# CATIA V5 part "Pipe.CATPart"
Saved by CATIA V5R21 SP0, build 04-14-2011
Part number: Pipe
Bounding box of the stored display mesh (mm): x -50 to 50, y 0 to 150, z -50 to 50
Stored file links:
  D:\CATIA V5R21 E-RESOURCES\CATIA-V5R21\catia-v5r21-Prts\c12_catia_v5r21_prt\c12_catia_v5r21figr_12-39\Pipe.CATPart
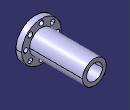
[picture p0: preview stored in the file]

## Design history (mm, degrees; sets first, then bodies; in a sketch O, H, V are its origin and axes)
Body1 (main body)
  Sketch1 on zx-plane, origin (0, 0, 0), H (-1, 0, 0), V (0, 0, 1)
    circle A1 centre (0, 0) radius 50
    point P1 (0, -50)
    circle A2 centre (0, 0) radius 30
    point P2 (0, -30)
    radius A1 = 50
    radius A2 = 30
    coincidence: A1 P1, P1 V, A2 P2, P2 V
  MultiPad1: profile Sketch1, domains (length 150; length 15)
  Sketch2 on face of MultiPad1, origin (0, 150, 0), H (-1, 0, 0), V (0, 0, 1)
    circle A1 centre (0, 0) radius 20
    point P1 (0, -20)
    radius A1 = 20
    coincidence: A1 P1, P1 V
  Pocket1: profile Sketch2, direction (0, -1, 0), through (limit type 3)
  Sketch3 on face of MultiPad1, origin (0, 0, 0), H (1, 0, 0), V (0, 0, 1)
    circle A1 centre (0, -40) radius 6
    point P1 (0, -40)
    radius A1 = 6
    distance H P1 = 40
    coincidence: P1 V
  Pocket2: profile Sketch3, direction (0, 1, 0), through (limit type 3)
  CircPattern1: of Pocket2, instances 8, angular step 45, axis from face of MultiPad1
